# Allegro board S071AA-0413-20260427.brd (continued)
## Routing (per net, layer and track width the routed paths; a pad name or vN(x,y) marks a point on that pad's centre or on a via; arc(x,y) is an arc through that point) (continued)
GNDA_REG: length 18.7
  L11_DPS w0.076: 147.87,222.61 147.87,214.68 v2(148.32,214.23)
  L11_DPS w0.203: 147.87,222.61 147.87,222.94 146.01,224.79 v1(146.01,230.92)
  BOTTOM w0.152: SH12.1 v1(146.01,230.92)
  vias: v1(92.98,288.29) v1(92.98,283.21) v1(93.76,279.15) v1(101.34,279.15) v1(102.12,288.29) v1(102.12,283.21) v1(106.38,285.83) v1(106.38,283.04) v1(112.45,271.67) v1(112.45,268.87) v1(122.94,258.74) v1(122.94,255.95) v1(136.51,248.16) v1(136.51,245.36) v1(177.02,218.6)
CSDPS225GS1: length 13.4
  L11_DPS w0.203: 129.81,335.28 128.61,336.48 126.7,336.48 125.85,335.62 125.85,329.08 CSDPS225.D2
CSDPS225GS16: length 13.3
  L11_DPS w0.203: 91.71,327.66 93.05,326.31 94.7,326.31 95.47,327.09 95.47,334.06 CSDPS225.A15
CSDPS225PS2: length 8.7
  L11_DPS w0.203: CSDPS225.A2 128.52,334.03 128.52,328.95 129.81,327.66
CSDPS225PS16: length 8.7
  L11_DPS w0.203: CSDPS225.A16 92.97,334.02 92.97,328.94 94.25,327.66
CSDPS229GS16: length 13.4
  L11_DPS w0.203: 18.05,327.66 16.63,329.08 16.63,335.62 17.48,336.48 19.39,336.48 CSDPS229.A15
CSDPS229PS16: length 8.7
  L11_DPS w0.203: 20.59,327.66 19.3,328.95 19.3,334.03 CSDPS229.A16
CSDPS425GS1: length 13.4
  L11_DPS w0.203: 129.81,345.44 128.61,346.64 126.7,346.64 125.85,345.78 125.85,339.24 CSDPS425.D2
CSDPS425GS15: length 13.3
  L11_DPS w0.203: CSDPS425.D16 93.05,336.47 94.7,336.47 95.47,337.25 95.47,344.22 94.25,345.44
CSDPS425PS2: length 8.7
  L11_DPS w0.203: 129.81,337.82 128.52,339.11 128.52,344.19 CSDPS425.A2
CSDPS425PS16: length 8.7
  L11_DPS w0.203: CSDPS425.A16 92.97,344.18 92.97,339.1 94.25,337.82
CSDPS429GS1: length 13.4
  L11_DPS w0.203: CSDPS429.D2 52.19,339.24 52.19,345.78 53.04,346.64 54.95,346.64 56.15,345.44
CSDPS429GS15: length 13.4
  L11_DPS w0.203: 20.59,345.44 19.39,346.64 17.48,346.64 16.63,345.78 16.63,339.24 CSDPS429.D16
CSDPS429PS2: length 8.7
  L11_DPS w0.203: CSDPS429.A2 54.86,344.19 54.86,339.11 56.15,337.82
CSDPS429PS16: length 8.7
  L11_DPS w0.203: 20.59,337.82 19.3,339.11 19.3,344.19 CSDPS429.A16
D231_MCB1_CT2: length 82.1
  L03_DIG w0.132: D231.17 13.04,370.91 13.04,314.98 v2(29.05,298.96)
D431_MCB1_A+: length 354.8
  L24_DIG w0.132: 74.57,190.88 73.7,191.75 54.6,191.75 K3.5 50.83,191 ; 74.57,190.88 K2.5 78.23,191.75 97.32,191.75 97.96,191.11 ; 74.57,190.88 74.57,195.71 K10.5 74.31,198.75 74.31,203.08 K12.5 74.52,206.17 74.52,210.9 K14.5 ; 97.96,191.11 K1.5 ; 97.96,191.11 97.96,195.48 K11.5 97.91,198.78 97.91,203.05 K13.5 97.96,206.35 97.96,210.72 K15.5 ; K7.5 50.8,210.8 50.8,206.27 K8.5 50.84,203.22 50.84,198.6 K9.5 50.83,195.59 50.83,191 ; D431.16 12.83,375.78 12.83,257.85 24.32,246.35 24.32,222.51 26.29,220.54 26.29,214.77 K4.5 27.08,210.71 27.08,206.36 K5.5 27.03,203.04 27.03,198.79 K6.5 27.21,195.6 27.21,190.99 K16.5 31.37,192.14 49.69,192.14 50.83,191
D431_MCB1_A-: length 328.2
  L24_DIG w0.132: 74.46,221.46 74.21,221.71 54.09,221.71 K18.5 50.62,221.68 ; 74.46,221.46 K19.5 77.84,221.84 97.71,221.84 98.16,221.39 ; 74.46,221.46 74.46,226.09 K23.5 74.41,229.13 74.41,233.66 K27.5 74.41,236.75 74.41,241.28 K31.5 ; D431.15 19.3,382.25 19.3,376.96 16.82,374.48 14.65,374.48 13.39,373.22 13.39,258.16 K29.5 27.06,241.16 27.06,236.86 K25.5 27.08,233.57 27.08,229.22 K21.5 26.88,225.75 26.88,221.8 K17.5 30.92,222.17 30.92,222.31 31.05,222.44 49.86,222.44 50.62,221.68 ; 98.16,221.39 K20.5 ; 98.16,221.39 98.16,226.16 K24.5 98,229.16 98,233.63 K28.5 98,236.78 98,241.25 K32.5 ; 50.62,221.68 50.62,225.87 K22.5 50.77,229.15 50.77,233.64 K26.5 50.57,236.97 50.57,241.06 K30.5
D431_MCB1_C+: length 380.2
  L24_DIG w0.132: K33.5 114.84,160 118.87,160 K37.5 122.61,159.85 133.96,159.85 K34.5 137.88,159.82 141.55,159.82 K38.5 ; K33.5 110.64,164.2 110.64,254.21 107.34,257.52 66.12,257.52 61.47,262.17 61.47,375.78 57.53,379.72 29.49,379.72 D431.12 ; K33.5 110.07,158.83 110.07,141.66 K35.5 115.17,136.56 134.04,136.56 K36.5
D431_MCB1_C-: length 387.1
  L24_DIG w0.132: D431.11 31.92,382.37 57.38,382.37 63.39,376.36 63.39,263.89 68.09,259.19 107.89,259.19 111.8,255.28 111.8,168.16 113.46,166.49 123.59,166.49 K41.5 129.57,163.08 149.86,163.08 K42.5 149.26,159.91 149.26,140.32 149.9,139.67 ; 149.9,139.67 144.77,139.67 K40.5 142.21,139.75 134.6,139.75 134.41,139.94 129.54,139.94 K43.5 127.05,139.92 121.9,139.92 K39.5 ; 149.9,139.67 K44.5
D431_MCB1_CT1: length 94
  L03_DIG w0.132: v2(29.05,297.94) 12.08,314.91 12.08,380.11 D431.17
D11616: length 208.2
  L03_DIG w0.132: v2(29.9,298.96) 130.42,298.96 160.24,328.78 160.24,386.03 D116.16
  BOTTOM w0.152: TR2.2 v2(29.9,298.96)
GPDPS1_1F: length 9.8
  L16_DPS w0.203: 241.57,18.24 DPS1.C03 ; DPS1.C03 241.57,19.86 ; DPS1.C03 240.76,19.05 ; DPS1.C03 242.38,19.05 ; 240.76,16.51 DPS1.B03 ; DPS1.B03 241.57,15.7 ; DPS1.B03 242.38,16.51 ; DPS1.B03 241.57,17.32 ; 241.57,13.16 DPS1.A03 ; DPS1.A03 241.57,14.78 ; DPS1.A03 242.38,13.97 ; DPS1.A03 240.76,13.97
  vias: v1(205.76,294.62)
GPDPS1_1GS: length 464.1
  L16_DPS w0.203: v1(194.58,294.32) 195.74,293.16 208.28,293.16 210.57,290.88 210.57,221.48 200.95,211.86 196.23,211.86 195.11,212.98 187.82,212.98 186.7,211.86 166.3,211.86 164.02,209.58 160.74,209.58 155.85,204.69 155.85,184.25 227.3,112.8 227.3,77.97 236.6,68.68 269.84,68.68 273.63,64.9 273.63,11.23 272.05,9.65 250.9,9.65 248.15,12.41 248.15,20.43 247.22,21.35 239.43,21.35 237.78,19.7 237.78,15.22 DPS1.A02
GPDPS1_1S: length 458.1
  L16_DPS w0.203: DPS1.C02 240.5,20.52 247.06,20.52 247.72,19.86 247.72,11.61 250.28,9.05 272.62,9.05 276.02,12.44 276.02,65.79 272.21,69.6 237.13,69.6 228.55,78.18 228.55,113.75 156.35,185.95 156.35,202.99 162.26,208.9 164.43,208.9 166.79,211.26 186.91,211.26 188.01,212.36 194.82,212.36 195.92,211.26 201.28,211.26 211.32,221.3 211.32,291.23 208.83,293.71 197.73,293.71 v1(197.12,294.32)
GPDPS1_2F: length 9.8
  L16_DPS w0.203: 250.92,13.97 DPS1.A07 ; DPS1.A07 251.73,13.16 ; DPS1.A07 251.73,14.78 ; DPS1.A07 252.54,13.97 ; DPS1.B07 252.54,16.51 ; DPS1.B07 250.92,16.51 ; DPS1.B07 251.73,17.32 ; DPS1.B07 251.73,15.7 ; DPS1.C07 252.54,19.05 ; DPS1.C07 251.73,18.24 ; DPS1.C07 251.73,19.86 ; DPS1.C07 250.92,19.05
  vias: v1(172.23,294.62)
GPDPS1_2GS: length 689.7
  L16_DPS w0.203: DPS1.A06 249.19,12.7 250.76,11.13 259.26,11.13 260.78,12.65 260.78,31.49 258.13,34.15 258.13,36.2 257.51,36.82 13.78,36.82 11.83,38.77 11.83,179.93 11.16,180.6 11.16,266.13 33.37,288.34 33.37,295.23 38.56,300.42 161.72,300.42 164.1,298.04 v1(164.1,294.32)
GPDPS1_2S: length 695.9
  L16_DPS w0.203: v1(166.64,294.32) 166.64,296.81 162.46,300.99 38.22,300.99 32.73,295.51 32.73,290.19 10.35,267.81 10.35,38.08 14.23,34.2 257.2,34.2 260.36,31.04 260.36,13.06 259.03,11.73 251.15,11.73 250.41,12.47 250.41,17.83 DPS1.C06
GPDPS1_3F: length 9.8
  L16_DPS w0.203: 266.16,16.51 DPS1.B13 ; DPS1.B13 266.97,15.7 ; DPS1.B13 266.97,17.32 ; DPS1.B13 267.78,16.51 ; 266.97,18.24 DPS1.C13 ; DPS1.C13 267.78,19.05 ; DPS1.C13 266.16,19.05 ; DPS1.C13 266.97,19.86 ; DPS1.A13 266.97,14.78 ; DPS1.A13 267.78,13.97 ; DPS1.A13 266.97,13.16 ; DPS1.A13 266.16,13.97
  vias: v1(48.28,294.62)
GPDPS1_3GS: length 535.8
  L16_DPS w0.203: DPS1.A12 263.26,15.14 263.26,29.85 260.6,32.5 260.6,41 259.88,41.72 20.76,41.72 12.45,50.04 12.45,264.53 38.01,290.09 38.01,293.41 v1(37.1,294.32)
GPDPS1_3S: length 532.3
  L16_DPS w0.203: DPS1.C12 264.43,30.28 263.14,31.57 263.14,41.15 261.99,42.3 21.25,42.3 13.16,50.38 13.16,262.71 40.82,290.37 40.82,293.13 v1(39.64,294.32)
GPDPS1_4F: length 9.8
  L11_DPS w0.203: 277.13,15.7 DPS1.B17 ; DPS1.B17 277.13,17.32 ; DPS1.B17 277.94,16.51 ; DPS1.B17 276.32,16.51 ; 276.32,13.97 DPS1.A17 ; DPS1.A17 277.13,13.16 ; DPS1.A17 277.94,13.97 ; DPS1.A17 277.13,14.78 ; 277.13,18.24 DPS1.C17 ; DPS1.C17 277.13,19.86 ; DPS1.C17 277.94,19.05 ; DPS1.C17 276.32,19.05
  vias: v1(149.88,294.62)
GPDPS1_4GS: length 413.6
  L11_DPS w0.203: v1(138.7,294.32) 140.34,294.32 141.44,293.22 268.44,293.22 270.15,291.51 270.15,104.63 268.27,102.75 268.27,24.5 273.35,19.42 273.35,15.21 DPS1.A16
GPDPS1_4S: length 405
  L11_DPS w0.203: DPS1.C16 270.76,22.88 270.76,291.91 268.97,293.71 141.85,293.71 v1(141.24,294.32)
GPDPS1_TRVB-: length 5.2
  TOP w0.152: SB1.2 258.04,13.12 258.04,15.28 DPS1.B09
GPDPS2_1F: length 9.8
  L11_DPS w0.203: 198.39,411.94 DPS2.B03 ; DPS2.B03 197.58,412.75 ; DPS2.B03 198.39,413.56 ; DPS2.B03 199.2,412.75 ; DPS2.A03 198.39,416.1 ; DPS2.A03 197.58,415.29 ; DPS2.A03 198.39,414.48 ; DPS2.A03 199.2,415.29 ; 197.58,410.21 DPS2.C03 ; DPS2.C03 198.39,411.02 ; DPS2.C03 198.39,409.4 ; DPS2.C03 199.2,410.21
  vias: v1(127.02,294.62)
GPDPS2_1GS: length 214.3
  L11_DPS w0.203: v1(115.84,294.32) 115.84,310.2 110.58,315.46 110.58,404.82 111.16,405.4 187.98,405.4 191.79,409.21 191.79,416.47 193.21,417.89 199.3,417.89 200.93,416.25 DPS2.A02
GPDPS2_1S: length 218.6
  L11_DPS w0.203: DPS2.C02 199.83,411.31 199.83,416.51 199.05,417.29 193.49,417.29 192.27,416.07 192.27,408.76 188.36,404.85 111.63,404.85 111.01,404.23 111.01,315.88 118.38,308.51 v1(118.38,294.32)
GPDPS2_2F: length 9.8
  L11_DPS w0.203: 187.42,412.75 DPS2.B07 ; DPS2.B07 189.04,412.75 ; DPS2.B07 188.23,411.94 ; DPS2.B07 188.23,413.56 ; DPS2.A07 189.04,415.29 ; DPS2.A07 188.23,416.1 ; DPS2.A07 188.23,414.48 ; DPS2.A07 187.42,415.29 ; DPS2.C07 189.04,410.21 ; DPS2.C07 188.23,411.02 ; DPS2.C07 188.23,409.4 ; DPS2.C07 187.42,410.21
  vias: v1(99.08,294.62)
GPDPS2_2GS: length 229.2
  L11_DPS w0.203: DPS2.A06 190.77,417.4 187.98,420.2 92.67,420.2 87.9,415.42 v1(87.9,294.32)
GPDPS2_2S: length 229.1
  L11_DPS w0.203: DPS2.C06 189.63,411.35 189.63,416.76 187.87,418.52 93.87,418.52 90.44,415.08 v1(90.44,294.32)
GPDPS2_3F: length 9.8
  L16_DPS w0.203: DPS2.B13 173.8,412.75 ; DPS2.B13 172.99,413.56 ; DPS2.B13 172.99,411.94 ; DPS2.B13 172.18,412.75 ; DPS2.A13 173.8,415.29 ; DPS2.A13 172.18,415.29 ; DPS2.A13 172.99,414.48 ; DPS2.A13 172.99,416.1 ; DPS2.C13 173.8,410.21 ; DPS2.C13 172.18,410.21 ; DPS2.C13 172.99,409.4 ; DPS2.C13 172.99,411.02
  vias: v1(235.73,294.62)
GPDPS2_3GS: length 184
  L16_DPS w0.203: v1(227.6,294.32) 227.6,297.8 211.64,313.76 211.64,378.45 202.77,387.32 168.65,387.32 166.09,389.87 164.8,389.87 164.1,390.58 164.1,416.38 166.73,419.01 173.27,419.01 175.53,416.75 DPS2.A12
GPDPS2_3S: length 185.9
  L16_DPS w0.203: DPS2.C12 174.41,411.33 174.41,417.08 173.39,418.1 167.49,418.1 166.32,416.92 166.32,390.46 166.96,389.82 202.01,389.82 212.59,379.24 212.59,314.52 230.14,296.97 v1(230.14,294.32)
GPDPS2_4F: length 5.1
  L09_DPS w0.203: DPS2.C17 DPS2.B17 DPS2.A17
GPDPS2_TRVB-: length 5.2
  TOP w0.152: SB13.2 181.88,416.26 181.88,414.02 DPS2.B09
GPDPS3_1F: length 5.1
  L09_DPS w0.203: DPS3.C03 DPS3.B03 DPS3.A03
GPDPS3_2F: length 5.1
  L09_DPS w0.203: DPS3.A07 DPS3.B07 DPS3.C07
GPDPS3_3F: length 5.1
  L09_DPS w0.203: DPS3.A13 DPS3.B13 DPS3.C13
GPDPS3_4F: length 5.1
  L09_DPS w0.203: DPS3.A17 DPS3.B17 DPS3.C17
GPDPS3_TRVB-: length 5.6
  TOP w0.152: SB14.2 110.73,12.74 110.73,15.27 DPS3.B09
GPDPS8_1F: length 5.1
  L09_DPS w0.203: DPS8.A03 DPS8.B03 DPS8.C03
GPDPS8_2F: length 5.1
  L09_DPS w0.203: DPS8.C07 DPS8.B07 DPS8.A07
GPDPS8_3F: length 5.1
  L09_DPS w0.203: DPS8.A13 DPS8.B13 DPS8.C13
GPDPS8_4F: length 5.1
  L09_DPS w0.203: DPS8.A17 DPS8.B17 DPS8.C17
GPDPS8_TRVB-: length 5
  TOP w0.152: DPS8.B09 34.58,413.99 34.58,416.14 SB15.2
S1_ADC1_VIN[0]: length 36
  L20_DIG w0.076: v2(141.92,207.03) 141.57,206.68
  L20_DIG w0.132: K1.8 119.9,192.02 119.9,199.14 127.22,206.45 141.34,206.45 141.57,206.68
S1_ADC1_VIN[1]: length 58.9
  L20_DIG w0.076: v2(141.92,207.83) 141.52,207.43 138.29,207.43
  L20_DIG w0.132: K2.8 96.69,192.43 96.69,197.79 98.85,199.95 118.53,199.95 126.01,207.43 138.29,207.43
S1_ADC1_VIN[2]: length 86.9
  L20_DIG w0.076: 138.29,208.23 141.52,208.23 v2(141.92,208.63)
  L20_DIG w0.132: K3.8 73.02,192.38 73.02,204.7 74.92,206.6 122.95,206.6 124.58,208.23 138.29,208.23
S1_ADC1_VIN[3]: length 96.5
  L18_DIG w0.076: v2(141.12,208.63) 140.72,208.23 138.29,208.23
  L18_DIG w0.132: 138.29,208.23 50.61,208.23 K4.8
S1_ADC1_VIN[4]: length 95.9
  L18_DIG w0.076: 138.29,207.43 140.72,207.43 v2(141.12,207.83)
  L18_DIG w0.132: 138.29,207.43 49.2,207.43 K5.8
S1_ADC1_VIN[5]: length 98.7
  L18_DIG w0.076: 140.77,206.68 v2(141.12,207.03)
  L18_DIG w0.132: K6.8 49.06,199.67 119.07,199.67 125.91,206.51 140.6,206.51 140.77,206.68
S1_ADC1_VIN[6]: length 72.1
  L07_DIG w0.076: 138.29,208.23 139.92,208.23 v2(140.32,208.63)
  L07_DIG w0.132: K7.8 74.23,208.23 138.29,208.23
S1_ADC1_VIN[7]: length 71.5
  L07_DIG w0.076: 138.29,207.43 139.92,207.43 v2(140.32,207.83)
  L07_DIG w0.132: 138.29,207.43 72.83,207.43 K8.8
S1_ADC1_VIN[8]: length 74.3
  L07_DIG w0.076: v2(140.32,207.03) 139.97,206.68
  L07_DIG w0.132: 139.97,206.68 139.82,206.53 125.52,206.53 118.96,199.97 72.99,199.97 K9.8
S1_ADC1_VIN[9]: length 49.9
  L05_DIG w0.076: 139.17,206.68 v2(139.52,207.03)
  L05_DIG w0.132: 139.17,206.68 138.94,206.45 125.64,206.45 119.09,199.9 96.54,199.9 K10.8
S1_ADC1_VIN[10]: length 25.5
  L03_DIG w0.132: v2(138.72,207.03) 127.29,207.03 K11.8
S1_ADC1_VIN[11]: length 47.1
  L05_DIG w0.076: v2(139.52,207.83) 139.12,207.43 138.29,207.43
  L05_DIG w0.132: K12.8 96.45,207.43 138.29,207.43
S1_ADC1_VIN[12]: length 22.6
  L03_DIG w0.132: K13.8 120.47,207.83 v2(138.72,207.83)
S1_ADC1_VIN[13]: length 47.6
  L05_DIG w0.076: v2(139.52,208.63) 139.12,208.23 138.29,208.23
  L05_DIG w0.132: 138.29,208.23 97.86,208.23 K14.8
S1_ADC1_VIN[14]: length 22.9
  L03_DIG w0.132: v2(138.72,208.63) 121.08,208.63 K15.8
S1_ADC1_VIN[15]: length 111.2
  L20_DIG w0.076: 138.29,209.03 141.52,209.03 v2(141.92,209.43)
  L20_DIG w0.132: K16.8 49.6,192.58 49.6,205.36 52.19,207.95 122.32,207.95 123.4,209.03 138.29,209.03
S1_ADC1_VIN[16]: length 99.3
  L18_DIG w0.076: 138.29,209.03 140.72,209.03 v2(141.12,209.43)
  L18_DIG w0.132: K17.8 51.96,214.5 119.12,214.5 124.59,209.03 138.29,209.03
S1_ADC1_VIN[17]: length 74.9
  L07_DIG w0.076: 138.29,209.03 139.92,209.03 v2(140.32,209.43)
  L07_DIG w0.132: K18.8 75.66,214.43 119.22,214.43 124.61,209.03 138.29,209.03
S1_ADC1_VIN[18]: length 50.5
  L05_DIG w0.076: v2(139.52,209.43) 139.12,209.03 138.29,209.03
  L05_DIG w0.132: 138.29,209.03 125.58,209.03 120.01,214.6 99.1,214.6 K19.8
S1_ADC1_VIN[19]: length 25.7
  L03_DIG w0.132: K20.8 127.9,209.43 v2(138.72,209.43)
S1_ADC1_VIN[20]: length 102.1
  L18_DIG w0.076: v2(141.12,210.23) 140.72,209.83 138.29,209.83
  L18_DIG w0.132: K21.8 51.58,222.5 107.51,222.5 114.29,215.72 120.41,215.72 126.3,209.83 138.29,209.83
S1_ADC1_VIN[21]: length 77.7
  L07_DIG w0.076: 138.29,209.83 139.92,209.83 v2(140.32,210.23)
  L07_DIG w0.132: 138.29,209.83 126,209.83 120.03,215.8 110.86,215.8 104.66,222 75.71,222 K22.8
S1_ADC1_VIN[22]: length 55.2
  L05_DIG w0.076: v2(139.52,210.23) 139.12,209.83 138.29,209.83
  L05_DIG w0.132: K23.8 98.8,222.53 117.47,222.53 118.84,221.16 118.84,217.91 126.91,209.83 138.29,209.83
S1_ADC1_VIN[23]: length 32
  L03_DIG w0.132: v2(138.72,210.23) 128.9,210.23 119.04,220.09 119.04,225.91 K24.8
S1_ADC1_VIN[24]: length 110.3
  L18_DIG w0.076: v2(141.12,211.03) 140.72,210.63 138.29,210.63
  L18_DIG w0.132: K25.8 51.48,230.23 117.62,230.23 119.42,228.42 119.42,219.25 128.04,210.63 138.29,210.63
S1_ADC1_VIN[25]: length 86.2
  L07_DIG w0.076: 138.29,210.63 139.92,210.63 v2(140.32,211.03)
  L07_DIG w0.132: 138.29,210.63 127.49,210.63 119.37,218.74 119.37,228.37 117.74,230 75.33,230 K26.8
S1_ADC1_VIN[26]: length 61.6
  L05_DIG w0.076: 138.29,210.63 139.12,210.63 v2(139.52,211.03)
  L05_DIG w0.132: K27.8 98.87,230.07 118.02,230.07 119.57,228.52 119.57,219.18 128.12,210.63 138.29,210.63
S1_ADC1_VIN[27]: length 38.5
  L03_DIG w0.132: K28.8 119.85,232.71 119.85,220.5 129.32,211.03 v2(138.72,211.03)
S1_ADC1_VIN[28]: length 116.5
  L18_DIG w0.076: v2(141.12,211.83) 140.72,211.43 138.29,211.43
  L18_DIG w0.132: 138.29,211.43 129.45,211.43 120.56,220.32 120.56,235.15 117.85,237.87 51.45,237.87 K29.8
S1_ADC1_VIN[29]: length 92.5
  L07_DIG w0.076: 138.29,211.43 139.92,211.43 v2(140.32,211.83)
  L07_DIG w0.132: 138.29,211.43 129.07,211.43 120.59,219.91 120.59,235.51 118.3,237.79 75.15,237.79 K30.8
S1_ADC1_VIN[30]: length 68.1
  L05_DIG w0.076: v2(139.52,211.83) 139.12,211.43 138.29,211.43
  L05_DIG w0.132: K31.8 99.02,237.54 119.27,237.54 120.54,236.27 120.54,220.6 129.71,211.43 138.29,211.43
S1_ADC1_VIN[31]: length 45.2
  L03_DIG w0.132: K32.8 120.64,239.55 120.64,220.7 129.51,211.83 v2(138.72,211.83)
S1_ADC2_VIN[0]: length 43.1
  L03_DIG w0.132: v2(143.52,207.03) 143.52,204.9 122.14,183.52 116.99,183.52 K33.8
S1_ADC2_VIN[1]: length 31.7
  L05_DIG w0.076: v2(143.52,207.83) 143.92,207.43 143.92,206.68
  L05_DIG w0.132: 143.92,206.68 143.92,187.59 K34.8
S1_ADC2_VIN[2]: length 65.1
  L07_DIG w0.076: v2(143.52,208.63) 143.92,208.23 143.92,206.68
  L07_DIG w0.132: K35.8 118.23,161.65 118.23,179.53 143.92,205.22 143.92,206.68
S1_ADC2_VIN[3]: length 56.7
  L18_DIG w0.076: 143.92,206.68 143.92,209.03 v2(143.52,209.43)
  L18_DIG w0.132: 143.92,206.68 143.92,185.89 140.87,182.84 140.87,161.18 K36.8
S1_ADC2_VIN[4]: length 37.2
  L03_DIG w0.132: v2(144.32,207.03) 144.32,203.23 K37.8
S1_ADC2_VIN[5]: length 28.9
  L05_DIG w0.076: 144.72,206.68 144.72,207.43 v2(144.32,207.83)
  L05_DIG w0.132: 144.72,206.68 144.72,180.77 K38.8
S1_ADC2_VIN[6]: length 62.3
  L07_DIG w0.076: 144.72,206.68 144.72,208.23 v2(144.32,208.63)
  L07_DIG w0.132: K39.8 125.7,161.5 125.7,182.48 144.72,201.5 144.72,206.68
S1_ADC2_VIN[7]: length 56.7
  L18_DIG w0.076: v2(144.32,209.43) 144.72,209.03 144.72,206.68
  L18_DIG w0.132: 144.72,206.68 144.72,186.54 148.08,183.18 148.08,160.76 K40.8
S1_ADC2_VIN[8]: length 34.4
  L03_DIG w0.132: K41.8 145.12,196.41 v2(145.12,207.03)
S1_ADC2_VIN[9]: length 30.7
  L05_DIG w0.076: v2(145.12,207.83) 145.52,207.43 145.52,206.68
  L05_DIG w0.132: 145.52,206.68 145.52,185.2 K42.8
S1_ADC2_VIN[10]: length 59.5
  L07_DIG w0.076: 145.52,206.68 145.52,208.23 v2(145.12,208.63)
  L07_DIG w0.132: K43.8 133.35,161.52 133.35,180.8 145.52,192.97 145.52,206.68
S1_ADC2_VIN[11]: length 55.7
  L18_DIG w0.076: 145.52,206.68 145.52,209.03 v2(145.12,209.43)
  L18_DIG w0.132: K44.8 149.13,158.23 149.13,183.36 145.52,186.97 145.52,206.68
S1_CBIT001: length 380.3
  TOP w0.305: K1.1 114.82,184.4 LD1.2
  L13_CBIT w0.305: K1.1 114.12,186.94 104.01,197.06 104.01,255.04 110.44,261.47 242.42,261.47 256.98,276.04 256.98,288.57 258.18,289.76 258.18,410.31 259.35,411.48
S1_CBIT002: length 207
  TOP w0.305: K2.1 91.2,184.4 LD2.2
  L13_CBIT w0.305: K2.1 93.74,155.57 159.5,89.81 159.5,18.57 162.83,15.24
S1_CBIT003: length 225.6
  TOP w0.305: K3.1 67.58,184.4 LD3.2
  L13_CBIT w0.305: K3.1 70.12,176.91 158.09,88.94 158.09,16.42 161.3,13.2 165.87,13.2 167.91,15.24
S1_CBIT004: length 254.6
  TOP w0.305: LD4.2 43.96,207.26 K4.1
  L13_CBIT w0.305: 99.33,414.02 98.07,412.76 98.07,326.98 93.13,322.03 66.84,322.03 40.65,295.84 40.65,212.99 43.84,209.8 K4.1
S1_CBIT005: length 261.5
  TOP w0.305: LD5.2 43.96,199.64 K5.1
  L13_CBIT w0.305: 96.79,411.48 95.56,410.25 95.56,327.47 92.3,324.21 63.57,324.21 38.88,299.52 38.88,207.16 43.85,202.18 K5.1
S1_CBIT006: length 285.8
  TOP w0.305: LD6.2 43.96,192.02 K6.1
  L13_CBIT w0.305: K6.1 44.05,194.56 36.28,202.34 36.28,301.35 86.74,351.81 86.74,414.26 89.67,417.19 113.94,417.19 117.11,414.02
S1_CBIT007: length 246
  TOP w0.305: K7.1 67.58,207.26 LD7.2
  L13_CBIT w0.305: K7.1 67.46,209.8 63.59,213.67 63.59,291.52 75.53,303.45 94.74,303.45 115.92,324.63 115.92,410.29 117.11,411.48
S1_CBIT008: length 259.7
  TOP w0.305: K8.1 67.58,199.64 LD8.2
  L13_CBIT w0.305: 114.57,414.02 113.15,412.6 113.15,324.62 94.5,305.97 74.11,305.97 58.91,290.77 58.91,210.75 67.47,202.18 K8.1
S1_CBIT009: length 265.2
  TOP w0.305: K9.1 67.58,192.02 LD9.2
  L13_CBIT w0.305: K9.1 67.67,194.56 57.39,204.85 57.39,292.86 73.22,308.69 94.25,308.69 110.77,325.22 110.77,410.23 112.03,411.48
S1_CBIT010: length 252.8
  TOP w0.305: LD10.2 91.2,192.02 K10.1
  L13_CBIT w0.305: K10.1 91.3,194.56 81.28,204.58 81.28,272.6 128.61,319.93 128.61,412.82 129.81,414.02
S1_CBIT011: length 373.6
  TOP w0.305: LD11.2 114.82,192.02 K11.1
  L13_CBIT w0.305: 261.89,414.02 260.66,412.8 260.66,275.48 243.22,258.04 112.22,258.04 106.01,251.83 106.01,203.47 114.92,194.56 K11.1
S1_CBIT012: length 362.5
  TOP w0.305: LD12.2 91.2,199.64 K12.1
  L13_CBIT w0.305: 244.11,411.48 242.83,410.2 242.83,305.2 234.03,296.41 234.03,287.91 222.52,276.4 95.08,276.4 83.95,265.26 83.95,209.33 91.09,202.18 K12.1
S1_CBIT013: length 362.9
  TOP w0.305: LD13.2 114.82,199.64 K13.1
  L13_CBIT w0.305: K13.1 114.72,202.18 107.81,209.09 107.81,247.88 114.02,254.08 244.78,254.08 262.04,271.35 262.04,291.22 263.18,292.36 263.18,410.23 264.43,411.48
S1_CBIT014: length 355.5
  TOP w0.305: LD14.2 91.2,207.26 K14.1
  L13_CBIT w0.305: K14.1 91.08,209.8 87.62,213.26 87.62,264.38 97.39,274.14 224.92,274.14 237.09,286.31 237.09,296.36 245.38,304.65 245.38,412.75 246.65,414.02
S1_CBIT015: length 357.1
  TOP w0.305: K15.1 114.82,207.26 LD15.2
  L13_CBIT w0.305: 266.97,411.48 265.8,410.31 265.8,292.53 266.85,291.47 266.85,269.97 249.06,252.18 115.75,252.18 109.78,246.21 109.78,214.73 114.7,209.8 K15.1
S1_CBIT016: length 307.6
  TOP w0.305: LD16.2 43.96,184.4 K16.1
  L13_CBIT w0.305: K16.1 43.5,186.94 33.74,196.7 33.74,303.14 84.3,353.7 84.3,415.59 88.18,419.47 119.28,419.47 124.73,414.02
S1_CBIT017: length 243.5
  TOP w0.305: LD17.2 43.96,214.88 K17.1
  L13_CBIT w0.305: 101.87,411.48 100.61,410.22 100.61,326.79 93.47,319.65 67.83,319.65 43.59,295.41 43.59,281.75 42.24,280.4 42.24,219.55 44.36,217.42 K17.1
S1_CBIT018: length 236.1
  TOP w0.305: K18.1 67.58,214.88 LD18.2
  L13_CBIT w0.305: K18.1 67.98,217.42 66.13,219.27 66.13,289.12 78.04,301.02 95.62,301.02 118.15,323.55 118.15,409.98 119.65,411.48
S1_CBIT019: length 349.7
  TOP w0.305: LD19.2 91.2,214.88 K19.1
  L13_CBIT w0.305: 249.19,411.48 247.94,410.23 247.94,304.67 245.56,302.29 245.56,281.32 238.2,273.96 234.81,273.96 233.19,272.34 100.39,272.34 89.48,261.43 89.48,219.55 91.61,217.42 K19.1
S1_CBIT020: length 352.3
  TOP w0.305: K20.1 114.82,214.88 LD20.2
  L13_CBIT w0.305: 269.51,414.02 268.3,412.81 268.3,282.41 269.31,281.4 269.31,268.32 249.63,248.64 141.06,248.64 140.59,249.11 135.93,249.11 135.46,248.64 115.37,248.64 111.43,244.7 111.43,221.23 115.23,217.42 K20.1
S1_CBIT021: length 234.8
  TOP w0.305: LD21.2 43.96,222.5 K21.1
  L13_CBIT w0.305: K21.1 50.7,229.25 50.7,276.98 52.53,278.81 52.53,292.25 71.77,311.49 94.13,311.49 108.19,325.55 108.19,412.72 109.49,414.02
S1_CBIT022: length 216.8
  TOP w0.305: K22.1 67.58,222.5 LD22.2
  L13_CBIT w0.305: K22.1 74.32,229.25 74.32,268.3 125.8,319.78 125.8,410.01 127.27,411.48
S1_CBIT023: length 341
  TOP w0.305: LD23.2 91.2,222.5 K23.1
  L13_CBIT w0.305: K23.1 97.94,229.25 97.94,253.81 107.74,263.61 139.87,263.61 140.88,262.59 145.06,262.59 146.08,263.61 239.07,263.61 255.53,280.07 255.53,412.74 256.81,414.02
S1_CBIT024: length 342
  TOP w0.305: K24.1 114.82,222.5 LD24.2
  L13_CBIT w0.305: 272.05,411.48 270.91,410.34 270.91,264.83 252.82,246.75 116.31,246.75 113.14,243.58 113.14,226.88 114.97,225.04 K24.1
S1_CBIT025: length 224.5
  TOP w0.305: LD25.2 43.96,230.12 K25.1
  L13_CBIT w0.305: 106.95,411.48 105.53,410.06 105.53,325.7 93.97,314.13 70.16,314.13 49.18,293.14 49.18,235.34 K25.1
S1_CBIT026: length 208.1
  TOP w0.305: LD26.2 67.58,230.12 K26.1
  L13_CBIT w0.305: 124.73,411.48 123.35,410.1 123.35,321.01 72.8,270.46 72.8,235.34 K26.1
S1_CBIT027: length 331
  TOP w0.305: K27.1 91.2,230.12 LD27.2
  L13_CBIT w0.305: 254.27,411.48 252.97,410.18 252.97,294.22 251.77,293.03 251.77,280.4 237.98,266.62 147.36,266.62 145.97,268 140.83,268 139.45,266.62 105.1,266.62 96.59,258.11 96.59,235.52 K27.1
S1_CBIT028: length 335.9
  TOP w0.305: K28.1 114.82,230.12 LD28.2
  L13_CBIT w0.305: K28.1 120.36,235.66 120.36,239.14 123.42,242.2 258.3,242.2 279.1,263.01 279.1,290.85 275.9,294.06 275.9,412.79 277.13,414.02
S1_CBIT029: length 219.8
  TOP w0.305: LD29.2 43.96,237.74 K29.1
  L13_CBIT w0.305: K29.1 48.04,241.82 48.04,276.66 46.64,278.05 46.64,294.29 69.4,317.04 93.74,317.04 103,326.3 103,412.61 104.41,414.02
S1_CBIT030: length 212.2
  TOP w0.305: LD30.2 67.58,237.74 K30.1
  L13_CBIT w0.305: K30.1 71.66,241.82 71.66,290.52 80.13,298.99 97.53,298.99 120.81,322.27 120.81,412.64 122.19,414.02
S1_CBIT031: length 326.1
  TOP w0.305: K31.1 91.2,237.74 LD31.2
  L13_CBIT w0.305: 251.73,414.02 250.44,412.73 250.44,285.88 246.91,282.36 246.91,279.8 236.39,269.28 117.23,269.28 115.64,267.69 110.84,267.69 109.24,269.28 102.96,269.28 94.57,260.89 94.57,251.73 95.52,250.77 95.52,242.06 K31.1
S1_CBIT032: length 322.9
  TOP w0.305: LD32.2 114.82,237.74 K32.1
  L13_CBIT w0.305: K32.1 121.38,244.3 255.84,244.3 274.67,263.13 274.67,290.92 273.31,292.28 273.31,410.2 274.59,411.48
S1_CBIT033: length 201.9
  TOP w0.305: LD33.2 118.13,177.04 K33.1
  L13_CBIT w0.305: 167.91,17.78 166.71,18.98 166.71,110.39 156.87,120.23 136.69,120.23 118.97,137.96 118.97,176.19 K33.1
S1_CBIT034: length 196.7
  TOP w0.305: K34.1 140.99,177.04 LD34.2
  L13_CBIT w0.305: K34.1 141.98,176.04 141.98,137.51 146.02,133.47 162.57,133.47 181.9,114.13 181.9,19.07 180.61,17.78
S1_CBIT035: length 177
  TOP w0.305: LD35.2 118.13,153.92 K35.1
  L13_CBIT w0.305: 165.37,17.78 164.19,18.96 164.19,109.3 155.16,118.33 136.38,118.33 117.39,137.32 117.39,154.66 K35.1
S1_CBIT036: length 174.6
  TOP w0.305: LD36.2 140.99,153.67 K36.1
  L13_CBIT w0.305: K36.1 140.14,154.51 140.14,137 145.67,131.47 161.97,131.47 179.33,114.11 179.33,16.5 178.07,15.24
S1_CBIT037: length 200.7
  TOP w0.305: K37.1 125.75,177.04 LD37.2
  L13_CBIT w0.305: 172.99,17.78 171.72,19.05 171.72,112.49 159.95,124.26 140.02,124.26 126.67,137.61 126.67,176.11 K37.1
S1_CBIT038: length 189.6
  TOP w0.305: K38.1 148.61,177.04 LD38.2
  L13_CBIT w0.305: K38.1 146.07,178.36 181.25,143.17 181.25,133.56 189.59,125.23 189.59,16.6 188.23,15.24
S1_CBIT039: length 178.5
  TOP w0.305: K39.1 125.75,153.92 LD39.2
  L13_CBIT w0.305: 170.45,15.24 169.19,16.5 169.19,111.35 158.18,122.36 139.39,122.36 124.93,136.81 124.93,154.74 K39.1
S1_CBIT040: length 164.1
  TOP w0.305: LD40.2 148.61,153.67 K40.1
  L13_CBIT w0.305: K40.1 184.44,117.84 184.44,16.53 183.15,15.24
S1_CBIT041: length 201.3
  TOP w0.305: LD41.2 133.37,177.04 K41.1
  L13_CBIT w0.305: K41.1 134.31,176.09 134.31,137.45 142.99,128.77 161.34,128.77 176.82,113.29 176.82,16.53 175.53,15.24
S1_CBIT042: length 184.9
  TOP w0.305: LD42.2 156.23,177.04 K42.1
  L13_CBIT w0.305: 190.77,17.78 192.06,19.07 192.06,126.94 186.77,132.23 186.77,143.51 153.69,176.59 K42.1
S1_CBIT043: length 174.1
  TOP w0.305: LD43.2 133.37,153.92 K43.1
  L13_CBIT w0.305: K43.1 132.6,154.69 132.6,137.19 142.76,127.04 160.22,127.04 174.14,113.12 174.14,19.17 175.53,17.78
S1_CBIT044: length 160.4
  TOP w0.305: LD44.2 156.23,153.67 K44.1
  L13_CBIT w0.305: K44.1 155.5,156.21 186.91,124.8 186.91,19 185.69,17.78
S1_CBIT045: length 204.5
  TOP w0.305: K45.8 182.51,209.12 183.18,209.79 LD45.2
  L13_CBIT w0.305: 193.31,15.24 194.62,16.55 194.62,128.67 190.5,132.79 190.5,202.8 184.18,209.12 K45.8
S1_CBIT046: length 209
  TOP w0.305: K46.8 182.51,216.23 182.84,216.56 LD46.2
  L13_CBIT w0.305: K46.8 182.54,216.23 194.31,204.46 194.31,137.22 197.13,134.4 197.13,19.06 195.85,17.78
S1_CSDPS1-1F:
  vias: v1(238.78,294.62)
S1_CSDPS1-1GS: length 565.1
  L16_DPS w0.203: 18.05,337.82 16.86,336.63 7.39,336.63 1.37,342.65 1.37,424.35 3.98,426.95 59.5,426.95 65.6,420.85 79.4,420.85 86.54,427.99 205.73,427.99 212.96,420.76 274.14,420.76 282.65,412.26 282.65,305.93 270.23,293.52 226.63,293.52 225.83,294.32 v1(225.06,294.32)
S1_CSDPS1-1S: length 554
  L16_DPS w0.203: 20.59,337.82 19.37,339.04 6.51,339.04 2.13,343.42 2.13,423.54 4.58,426 59.35,426 65.27,420.08 80.49,420.08 87.8,427.4 205.35,427.4 212.87,419.88 274,419.88 282.05,411.83 282.05,306.18 269.81,293.94 233.06,293.94 v1(232.68,294.32)
S1_CSDPS2-1F:
  vias: v1(123.97,294.62)
S1_CSDPS2-1GS: length 55.5
  L09_DPS w0.203: v1(113.3,294.32) 118.34,299.36 118.34,335.57 119.04,336.26 128.83,336.26 129.81,335.28
S1_CSDPS2-1S: length 46.2
  L09_DPS w0.203: v1(120.92,294.32) 120.92,333.33 121.79,334.21 126.2,334.21 127.27,335.28
S1_CSDPS3-1F:
  vias: v1(146.83,294.62)
S1_CSDPS3-1GS: length 50.1
  L09_DPS w0.203: 127.27,337.82 128.3,336.78 133.36,336.78 136.16,333.98 v1(136.16,294.32)
S1_CSDPS3-1S: length 52
  L09_DPS w0.203: v1(143.78,294.32) 137.29,300.81 137.29,334.9 134.37,337.82 129.81,337.82
S1_CSDPS4-1F:
  vias: v1(45.23,294.62)
S1_CSDPS4-1GS: length 67.7
  L09_DPS w0.203: v1(34.56,294.32) 34.56,298.78 31.65,301.68 16.61,301.68 12.03,306.27 12.03,333.56 15.04,336.57 19.3,336.57 20.59,335.28
S1_CSDPS4-1S: length 68
  L09_DPS w0.203: v1(42.18,294.32) 42.18,297.42 37.09,302.51 17.39,302.51 13.03,306.87 13.03,332.64 14.68,334.3 17.07,334.3 18.05,335.28
S1_CSDPS5-1F:
  vias: v1(96.03,294.62)
S1_CSDPS5-1GS: length 50
  L09_DPS w0.203: 94.25,335.28 93.17,336.36 87.8,336.36 85.36,333.92 v1(85.36,294.32)
S1_CSDPS5-1S: length 45.8
  L09_DPS w0.203: v1(92.98,294.32) 87.78,299.52 87.78,333.21 88.86,334.29 90.72,334.29 91.71,335.28
S1_CSDPS6-1F:
  vias: v1(175.28,294.62)
S1_CSDPS6-1GS: length 126.4
  L16_DPS w0.203: 91.71,337.82 92.73,338.84 149.09,338.84 174.03,313.9 174.03,293.69 173.54,293.2 169.33,293.2 168.92,293.62 163.45,293.62 162.75,294.32 v1(161.56,294.32)
S1_CSDPS6-1S: length 113.1
  L16_DPS w0.203: v1(169.18,294.32) 169.84,293.66 173.03,293.66 173.42,294.05 173.42,313.09 149.93,336.58 95.49,336.58 94.25,337.82
S1_CSDPS7-1F:
  vias: v1(202.71,294.62)
S1_CSDPS7-1GS: length 236.1
  L16_DPS w0.203: v1(192.04,294.32) 192.04,299.29 185.31,306.03 185.31,325.06 184.23,326.13 184.23,353.7 183.41,354.52 182.84,354.52 180.47,356.89 162.76,356.89 144.97,374.67 88.25,374.67 86.44,376.48 68.3,376.48 61.56,369.74 61.56,341.7 56.5,336.64 54.79,336.64 53.61,337.82
S1_CSDPS7-1S: length 238
  L16_DPS w0.203: v1(199.66,294.32) 198.46,294.32 186.16,306.62 186.16,325.23 184.68,326.71 184.68,355.43 182.68,357.44 163.43,357.44 143.7,377.17 67.96,377.17 60.37,369.57 60.37,342.04 56.15,337.82
S1_DCH001: length 106.9
  L03_DIG w0.132: K1.4 68.93,156.29 68.93,132.79 55.18,119.05 55.18,100.63 53.61,99.06
S1_DCH002: length 101.4
  L05_DIG w0.132: K2.4 69.74,180.72 69.74,133.78 44.74,108.79 44.74,100.36 43.45,99.06
S1_DCH003: length 122.4
  L07_DIG w0.132: K3.4 65.75,173.53 65.75,124.18 52.34,110.77 52.34,77.47 51.07,76.2
S1_DCH004: length 142.6
  L20_DIG w0.132: 35.83,76.2 36.82,77.19 36.82,113.97 22.44,128.35 22.44,203.53 K4.4
S1_DCH005: length 131.1
  L20_DIG w0.132: K5.4 25.49,198.96 25.49,128.45 39.54,114.4 39.54,79.91 38.37,78.74
S1_DCH006: length 125.6
  L20_DIG w0.132: K6.4 47.87,175.41 47.87,120.35 44.69,117.17 44.69,79.98 43.45,78.74
S1_DCH007: length 145.6
  L07_DIG w0.132: 45.99,76.2 47.28,77.5 47.28,109.17 45.76,110.69 45.76,180.54 40.76,185.55 40.76,204.9 43.09,207.24 49.77,207.24 K7.4
S1_DCH008: length 126.6
  L07_DIG w0.132: 48.53,78.74 49.77,79.98 49.77,109.7 47.84,111.63 47.84,180.59 49.67,182.42 49.67,199.52 K8.4
S1_DCH009: length 129
  L07_DIG w0.132: K9.4 68.87,178.03 68.87,123.9 54.83,109.85 54.83,79.96 53.61,78.74
S1_DCH010: length 116.3
  L05_DIG w0.132: K10.4 73.73,192.33 67.3,192.33 64.96,189.99 64.96,133.78 42.2,111.02 42.2,97.82 40.91,96.52
S1_DCH011: length 123.6
  L03_DIG w0.132: 51.07,96.52 52.16,97.61 52.16,120.35 66.13,134.32 66.13,170.36 87.9,192.13 97.15,192.13 K11.4
S1_DCH012: length 123.3
  L05_DIG w0.132: 38.37,99.06 39.61,100.3 39.61,112.95 48.86,122.2 48.86,169.6 62.7,183.44 62.7,196.77 65.9,199.97 73.75,199.97 K12.4
S1_DCH013: length 143.2
  L03_DIG w0.132: 48.53,99.06 49.9,100.43 49.9,119.89 48.61,121.18 48.61,167.89 63.24,182.52 63.24,196.34 66.82,199.92 97.32,199.92 K13.4
S1_DCH014: length 134.8
  L05_DIG w0.132: K14.4 73.42,207.26 65.06,207.26 60.06,202.26 60.06,184.89 46.12,170.94 46.12,123.49 37.12,114.5 37.12,97.82 35.83,96.52
S1_DCH015: length 155.5
  L03_DIG w0.132: K15.4 97.3,207.52 64.81,207.52 59.53,202.23 59.53,184.99 45.94,171.4 45.94,120.45 47.11,119.28 47.11,97.64 45.99,96.52
S1_DCH016: length 116.8
  L20_DIG w0.132: 40.91,76.2 42.1,77.39 42.1,115.93 28.72,129.31 K16.4
S1_DCH017: length 148.9
  L18_DIG w0.132: 30.75,76.2 32.04,77.5 32.04,114.38 28.03,118.39 28.03,163.5 34.99,170.46 34.99,211.15 K17.4
S1_DCH018: length 155.4
  L07_DIG w0.132: 23.13,78.74 24.35,79.96 24.35,109.04 30.57,115.27 30.57,179.3 37.71,186.44 37.71,210.72 42.18,215.19 50.1,215.19 K18.4
S1_DCH019: length 156.8
  L05_DIG w0.132: 33.29,99.06 34.58,100.36 34.58,119.53 30.32,123.8 30.32,160.05 39.89,169.62 39.89,210.74 44.09,214.93 73.47,214.93 K19.4
S1_DCH020: length 182.9
  L03_DIG w0.132: 23.13,99.06 21.86,100.33 21.86,146.86 39.89,164.9 39.89,211.96 42.84,214.91 97.07,214.91 K20.4
S1_DCH021: length 155.9
  L18_DIG w0.132: 33.29,78.74 34.51,79.96 34.51,115.77 30.37,119.91 30.37,160.43 38.47,168.53 38.47,215.29 K21.4
S1_DCH022: length 168
  L07_DIG w0.132: 20.59,76.2 21.83,77.44 21.83,110.62 28.46,117.25 28.46,180.67 34.03,186.23 34.03,216.97 39.64,222.58 49.88,222.58 K22.4
S1_DCH023: length 169.3
  L05_DIG w0.132: K23.4 73.37,222.45 41.19,222.45 35.42,216.69 35.42,170.21 28.13,162.92 28.13,122.78 32.02,118.9 32.02,97.79 30.75,96.52
S1_DCH024: length 196.2
  L03_DIG w0.132: K24.4 97.09,222.55 39.16,222.55 35.45,218.85 35.45,165.23 19.34,149.12 19.34,97.76 20.59,96.52
S1_DCH025: length 157.3
  L18_DIG w0.132: K25.4 25.64,229.59 25.64,117.25 29.43,113.46 29.43,79.96 28.21,78.74
S1_DCH026: length 180.9
  L07_DIG w0.132: K26.4 49.75,230.07 27.96,230.07 25.75,227.86 25.75,119.05 19.32,112.62 19.32,80.01 18.05,78.74
S1_DCH027: length 182.9
  L05_DIG w0.132: 28.21,99.06 29.58,100.43 29.58,117.96 25.49,122.05 25.49,226.77 28.92,230.2 73.5,230.2 K27.4
S1_DCH028: length 210
  L03_DIG w0.132: 18.05,99.06 15.43,101.68 15.43,151.13 25.77,161.47 25.77,227.89 27.93,230.05 96.97,230.05 K28.4
S1_DCH029: length 168.4
  L18_DIG w0.132: K29.4 23.28,234.85 23.28,116.71 26.96,113.03 26.96,77.5 25.67,76.2
S1_DCH030: length 192
  L07_DIG w0.132: K30.4 49.72,237.67 28.06,237.67 23.21,232.82 23.21,120.65 16.8,114.25 16.8,77.5 15.51,76.2
S1_DCH031: length 195.8
  L05_DIG w0.132: K31.4 73.5,237.82 25.62,237.82 23.18,235.38 23.18,121.13 26.94,117.37 26.94,97.79 25.67,96.52
S1_DCH032: length 220.8
  L03_DIG w0.132: K32.4 97.25,237.95 28.41,237.95 23.26,232.79 23.26,163.14 13.17,153.06 13.17,98.86 15.51,96.52
S1_DCH033: length 108
  L03_DIG w0.132: 178.07,96.52 176.84,97.75 176.84,120.97 153.92,143.9 125.23,143.9 118.04,151.09 118.04,159.34 K33.4
S1_DCH034: length 93.3
  L03_DIG w0.132: 185.69,99.06 184.46,100.29 184.46,128.44 161.19,151.72 142.42,151.72 140.71,153.43 140.71,159.54 K34.4
S1_DCH035: length 71.7
  L03_DIG w0.132: K35.4 130.37,123.9 147.43,123.9 161.77,109.57 161.77,97.58 162.83,96.52
S1_DCH036: length 54.7
  L03_DIG w0.132: K36.4 144.59,132.29 148.08,132.29 169.29,111.07 169.29,100.22 170.45,99.06
S1_DCH037: length 100.8
  L03_DIG w0.132: K37.4 125.5,159.5 125.5,152.6 131.26,146.84 155.73,146.84 179.39,123.18 179.39,100.28 180.61,99.06
S1_DCH038: length 88.1
  L03_DIG w0.132: K38.4 149.88,157.98 159.03,157.98 187.01,130 187.01,97.74 188.23,96.52
S1_DCH039: length 64.3
  L03_DIG w0.132: K39.4 135.55,126.34 147.87,126.34 164.16,110.05 164.16,100.27 165.37,99.06
S1_DCH040: length 53.1
  L03_DIG w0.132: K40.4 171.77,112.72 171.77,97.73 172.99,96.52
S1_DCH041: length 98.9
  L03_DIG w0.132: 183.15,96.52 181.94,97.73 181.94,125.36 157.99,149.31 137.55,149.31 132.96,153.89 132.96,159.66 K41.4
S1_DCH042: length 81.7
  L03_DIG w0.132: K42.4 159.87,161.8 189.53,132.14 189.53,100.3 190.77,99.06
S1_DCH043: length 62.2
  L03_DIG w0.132: K43.4 140.09,129.42 148.01,129.42 166.71,110.72 166.71,97.72 167.91,96.52
S1_DCH044: length 48.4
  L03_DIG w0.132: 175.53,99.06 174.41,100.18 174.41,117.71 K44.4
S1_DCH045: length 185.7
  L03_DIG w0.076: v2(153.92,212.63) 155.01,213.72
  L03_DIG w0.132: 239.03,99.06 240.31,100.34 240.31,176.79 196.98,220.12 174.73,220.12 168.61,214 155.29,214 155.01,213.72
S1_DCH046: length 168.3
  L03_DIG w0.132: v2(153.92,211.83) 155.73,210.02 167.7,210.02 207.17,170.55 207.17,90.53 199.72,83.08 199.72,77.53 198.39,76.2
S1_DCH047: length 168.6
  L07_DIG w0.076: 154.27,214.63 152.72,214.63 v2(152.32,214.23)
  L07_DIG w0.132: 154.27,214.63 167.38,214.63 174.23,221.48 177.39,221.48 234.55,278.64 234.55,280.06 253.06,298.56 253.06,328.99 254.27,330.2
S1_DCH048: length 206.2
  L24_DIG w0.132: v2(153.92,211.03) 155.96,208.99 166.23,208.99 220.47,154.75 220.47,117.1 227.09,110.49 227.09,77.99 235.77,69.31 243.54,69.31 250.45,62.4 250.45,57.16 251.73,55.88
S1_DCH049: length 167.4
  L07_DIG w0.076: 154.27,215.43 152.72,215.43 v2(152.32,215.03)
  L07_DIG w0.132: 251.73,332.74 250.48,331.49 250.48,298.61 238.56,286.7 237.74,286.7 166.48,215.43 154.27,215.43
S1_DCH050: length 220.2
  L22_DIG w0.076: v2(153.12,212.63) 153.52,213.03 154.44,213.03 155.13,213.72
  L22_DIG w0.132: 155.13,213.72 155.19,213.77 168.76,213.77 175.28,220.28 199.29,220.28 200.67,218.91 202.06,218.91 260.66,160.3 260.66,77.43 261.89,76.2
S1_DCH051: length 173.8
  L18_DIG w0.076: 154.27,215.43 151.92,215.43 v2(151.52,215.03)
  L18_DIG w0.132: 264.43,330.2 263.12,328.89 263.12,307.55 240.41,284.84 240.41,283.74 237.81,281.14 237.05,281.14 179.19,223.28 175.67,223.28 167.82,215.43 154.27,215.43
S1_DCH052: length 207.1
  L22_DIG w0.076: 154.27,211.43 153.52,211.43 v2(153.12,211.83)
  L22_DIG w0.132: 254.27,58.42 243.84,68.85 236.41,68.85 230,75.27 230,147.64 167.1,210.54 155.16,210.54 154.27,211.43
S1_DCH053: length 242.9
  L18_DIG w0.076: 154.27,213.83 151.92,213.83 v2(151.52,213.43)
  L18_DIG w0.132: 269.51,391.16 268.33,389.98 268.33,302.43 186.83,220.93 175.59,220.93 168.49,213.83 154.27,213.83
S1_DCH054: length 205.9
  L05_DIG w0.076: v2(153.12,210.23) 153.52,209.83 154.27,209.83
  L05_DIG w0.132: 154.27,209.83 163.24,209.83 224.3,148.77 224.3,85.02 208.54,69.27 195.16,69.27 188.23,76.2
S1_DCH055: length 195.1
  L18_DIG w0.076: v2(151.52,211.03) 151.92,210.63 154.27,210.63
  L18_DIG w0.132: 266.97,96.52 262.52,92.07 234.78,92.07 222.36,104.48 222.36,153.17 164.9,210.63 154.27,210.63
S1_DCH056: length 197.9
  L22_DIG w0.076: v2(153.12,209.43) 153.52,209.03 154.27,209.03
  L22_DIG w0.132: 154.27,209.03 161.51,209.03 182.94,187.6 185.47,187.6 224.73,148.34 224.73,72.67 233.26,64.14 238.39,64.14 244.11,58.42
S1_DCH057: length 179.8
  L07_DIG w0.076: v2(152.32,211.03) 152.72,210.63 154.27,210.63
  L07_DIG w0.132: 154.27,210.63 165.26,210.63 226.38,149.51 226.38,101.55 249.19,78.74
S1_DCH058: length 200.2
  L24_DIG w0.132: 246.65,55.88 245.39,57.14 245.39,62.02 241.91,65.5 234.72,65.5 224.84,75.39 224.84,107.53 210.57,121.8 210.57,157.1 176.17,191.49 176.17,194.01 162.22,207.97 155.38,207.97 v2(153.92,209.43)
S1_DCH059: length 213.9
  L20_DIG w0.076: v2(152.32,210.23) 152.72,209.83 154.27,209.83
  L20_DIG w0.132: 154.27,209.83 163.2,209.83 220.51,152.51 220.51,64.86 207.66,52.01 197.18,52.01 193.31,55.88
S1_DCH060: length 133.6
  L03_DIG w0.132: v2(153.92,208.63) 156.3,206.25 162.42,206.25 178.95,189.72 178.95,175.5 202.16,152.28 202.16,100.29 200.93,99.06
S1_DCH061: length 174.3
  L07_DIG w0.076: v2(152.32,213.43) 152.72,213.83 154.27,213.83
  L07_DIG w0.132: 256.81,332.74 255.54,331.47 255.54,298.99 237.12,280.57 237.12,278.3 179,220.18 174.06,220.18 167.71,213.83 154.27,213.83
S1_DCH062: length 180.6
  L18_DIG w0.076: v2(151.52,214.23) 151.92,214.63 154.27,214.63
  L18_DIG w0.132: 266.97,332.74 265.82,331.59 265.82,305.36 238.23,277.77 238.23,276.63 235.82,274.21 234.96,274.21 182.73,221.99 175.51,221.99 168.16,214.63 154.27,214.63
S1_DCH063: length 202.8
  L22_DIG w0.076: v2(153.12,211.03) 153.52,210.63 154.27,210.63
  L22_DIG w0.132: 154.27,210.63 155.07,209.83 165.64,209.83 227.24,148.24 227.24,74.02 235.11,66.15 241.46,66.15 249.19,58.42
S1_DCH064: length 161.7
  L03_DIG w0.132: v2(153.92,210.23) 155.65,208.5 164.76,208.5 204.86,168.4 204.86,92.95 197.16,85.25 197.16,80.05 195.85,78.74
S1_DCH065: length 225.1
  L22_DIG w0.076: v2(153.12,213.43) 153.52,213.83 154.27,213.83
  L22_DIG w0.132: 154.27,213.83 154.95,214.52 167.73,214.52 174.8,221.59 202.88,221.59 265.77,158.7 265.77,77.4 266.97,76.2
S1_DCH066: length 237.4
  L24_DIG w0.132: 264.43,58.42 263.29,59.56 263.29,125.85 240.67,148.47 240.67,178.49 198.16,221.01 174.5,221.01 167.32,213.83 154.32,213.83 v2(153.92,213.43)
S1_DCH067: length 204.3
  L05_DIG w0.076: v2(153.12,214.23) 153.52,214.63 154.27,214.63
  L05_DIG w0.132: 154.27,214.63 167.23,214.63 175.22,222.62 211.75,222.62 255.57,178.79 255.57,100.36 254.27,99.06
S1_DCH068: length 192.8
  L03_DIG w0.132: v2(153.92,214.23) 154.54,214.85 166.54,214.85 173.4,221.71 200.31,221.71 242.83,179.19 242.83,97.78 241.57,96.52
S1_DCH069: length 202.1
  L03_DIG w0.132: 246.65,96.52 247.94,97.81 247.94,136.19 247.04,137.08 247.04,183.9 205.25,225.7 169.27,225.7 164.25,220.68 161.06,220.68 158.6,218.22 154.71,218.22 v2(153.92,217.43)
S1_DCH070: length 246.7
  L24_DIG w0.132: 269.51,58.42 268.32,59.61 268.32,130.98 246.81,152.49 246.81,181.64 203.74,224.71 170.76,224.71 162.68,216.63 v2(153.92,216.63)
S1_DCH071: length 194.3
  L03_DIG w0.132: v2(153.92,215.83) 164.32,215.83 171.75,223.26 202.92,223.26 245.31,180.86 245.31,100.26 244.11,99.06
S1_DCH072: length 244.7
  L24_DIG w0.132: 266.97,55.88 265.82,57.03 265.82,128.4 244.05,150.17 244.05,180.39 201.86,222.59 173.84,222.59 166.28,215.03 v2(153.92,215.03)
S1_DCH073: length 247.6
  L22_DIG w0.076: v2(153.12,216.63) 153.52,217.03 154.27,217.03
  L22_DIG w0.132: 277.13,373.38 275.92,372.17 275.92,299.17 278.47,296.62 278.47,279.01 226.93,227.47 175.88,227.47 164.83,216.42 156.03,216.42 155.42,217.03 154.27,217.03
S1_DCH074: length 212.4
  L05_DIG w0.076: 154.27,216.23 153.52,216.23 v2(153.12,215.83)
  L05_DIG w0.132: 154.27,216.23 166.72,216.23 176.19,225.7 213.02,225.7 257.3,181.43 257.3,137.48 258.13,136.65 258.13,97.84 256.81,96.52
S1_DCH075: length 231.3
  L22_DIG w0.076: 154.27,215.43 153.52,215.43 v2(153.12,215.03)
  L22_DIG w0.132: 272.05,76.2 270.78,77.47 270.78,157.4 203.46,224.72 175.96,224.72 166.66,215.43 154.27,215.43
S1_DCH076: length 162.3
  L07_DIG w0.076: 154.27,217.03 152.72,217.03 v2(152.32,216.63)
  L07_DIG w0.132: 246.65,332.74 245.41,331.5 245.41,305.73 236.69,297.01 236.69,291.26 164.36,218.93 164.36,218.2 163.72,217.56 163.24,217.56 162.67,218.12 161.62,218.12 161.05,217.56 160.23,217.56 159.67,218.12 156.55,218.12 155.46,217.03 154.27,217.03
S1_DCH077: length 161.4
  L07_DIG w0.076: 154.27,216.23 152.72,216.23 v2(152.32,215.83)
  L07_DIG w0.132: 154.27,216.23 164.54,216.23 247.91,299.6 247.91,328.92 249.19,330.2
S1_DCH078: length 167.2
  L18_DIG w0.076: 154.27,217.03 151.92,217.03 v2(151.52,216.63)
  L18_DIG w0.132: 259.35,330.2 258.12,328.97 258.12,309.82 165.05,216.75 159.17,216.75 157.85,218.06 155.3,218.06 154.27,217.03
S1_DCH079: length 172.2
  L18_DIG w0.076: 154.27,216.23 151.92,216.23 v2(151.52,215.83)
  L18_DIG w0.132: 261.89,332.74 260.71,331.56 260.71,308.63 238.73,286.65 237.7,286.65 167.28,216.23 154.27,216.23
S1_DCH080: length 252.1
  L20_DIG w0.076: 154.27,213.84 151.13,213.84 v2(150.72,213.43)
  L20_DIG w0.132: 154.27,213.84 169.03,213.84 175.35,220.15 198.76,220.15 200.2,218.71 202.93,218.71 240.23,181.41 240.23,39.3 239.03,38.1
S1_DCH081: length 258.8
  L20_DIG w0.076: v2(150.72,214.23) 151.13,214.64 154.27,214.64
  L20_DIG w0.132: 154.27,214.64 168.33,214.64 175.22,221.53 204.02,221.53 242.67,182.87 242.67,36.66 241.57,35.56
S1_DCH082: length 260.9
  L20_DIG w0.076: v2(150.72,215.03) 151.13,215.44 154.27,215.44
  L20_DIG w0.132: 244.11,38.1 245.26,39.25 245.26,184.79 206.97,223.08 175.42,223.08 167.78,215.44 154.27,215.44
S1_DCH083: length 230.3
  L20_DIG w0.076: 154.27,216.24 151.13,216.24 v2(150.72,215.83)
  L20_DIG w0.132: 251.73,76.2 253.04,77.51 253.04,128.13 250.95,130.22 250.95,183.31 208.7,225.56 176.07,225.56 166.75,216.24 154.27,216.24
S1_DCH084: length 238.3
  L20_DIG w0.076: v2(150.72,216.63) 151.13,217.04 154.27,217.04
  L20_DIG w0.132: 154.27,217.04 155.17,217.04 156.44,218.31 157.49,218.31 159,216.8 164.85,216.8 167.1,219.04 167.98,219.04 177.87,228.94 209.19,228.94 256.16,181.97 256.16,129.9 258,128.06 258,77.39 256.81,76.2
S1_DCH085: length 171
  L07_DIG w0.076: v2(139.52,219.03) 139.12,219.43 138.55,219.43 138.29,219.68
  L07_DIG w0.132: 138.29,219.68 137.8,220.18 137.8,223.13 138.55,223.88 138.55,228.43 137.17,229.81 137.17,241.43 135.48,243.12 135.48,256.99 165.47,286.98 165.47,312.24 174.32,321.08 174.32,369.63 175.53,370.84
S1_DCH086: length 192.3
  L18_DIG w0.076: v2(140.32,218.23) 139.92,218.63 138.29,218.63
  L18_DIG w0.132: 175.53,391.16 174.25,389.88 174.25,314.86 135.66,276.28 135.66,233.67 137.71,231.62 137.71,219.21 138.29,218.63
S1_DCH087: length 126.7
  L03_DIG w0.132: 175.53,330.2 174.24,328.92 174.24,308.29 150.98,285.02 149.7,285.02 145.79,281.11 145.79,279.18 143.29,276.68 142.64,276.68 137.84,271.88 137.84,221.51 v2(138.72,220.63)
S1_DCH088: length 191.3
  L18_DIG w0.076: 140.72,222.61 140.72,220.23 v2(140.32,219.83)
  L18_DIG w0.132: 180.61,391.16 179.31,389.86 179.31,313.69 147.85,282.23 146.66,282.23 137.66,273.23 137.66,244.27 138.54,243.39 138.54,229.5 139.75,228.3 139.75,223.98 140.72,223.01 140.72,222.61
S1_DCH089: length 227.1
  L20_DIG w0.076: 141.53,222.58 141.53,219.44 v2(141.12,219.03)
  L20_DIG w0.132: 261.89,353.06 260.63,351.8 260.63,294.34 238.21,271.91 164.74,271.91 142.96,250.13 142.96,224.64 141.53,223.21 141.53,222.58
S1_DCH090: length 247.3
  L24_DIG w0.132: 249.19,391.16 247.97,389.94 247.97,305.18 230.85,288.05 230.85,286.54 208.8,264.49 154.61,264.49 140.32,250.2 140.32,237.48 138.43,235.59 138.43,229.64 140.32,227.75 v2(140.32,222.23)
S1_DCH091: length 170.5
  L07_DIG w0.076: 140.72,222.61 140.72,221.03 v2(140.32,220.63)
  L07_DIG w0.132: 183.15,373.38 181.97,372.2 181.97,318.37 173.79,310.19 173.79,286.24 142.39,254.84 142.39,224.27 140.72,222.61
S1_DCH092: length 191.2
  L18_DIG w0.076: v2(141.92,219.83) 142.32,220.23 142.32,222.58
  L18_DIG w0.132: 142.32,222.58 142.76,223.02 142.76,237.61 140.64,239.73 140.64,268.18 142.76,270.3 142.76,271.31 163.17,291.72 163.17,292.37 184.44,313.65 184.44,389.91 185.69,391.16
S1_DCH093: length 240.6
  L24_DIG w0.132: v2(138.72,219.83) 137.37,221.18 137.37,254.34 152.18,269.15 194.02,269.15 204.54,279.67 204.54,281.13 242.94,319.52 242.94,389.99 244.11,391.16
S1_DCH094: length 172.8
  L07_DIG w0.076: 138.37,222.61 138.37,220.46 138.6,220.23 139.12,220.23 v2(139.52,219.83)
  L07_DIG w0.132: 178.07,373.38 176.75,372.06 176.75,320.37 167.88,311.49 167.88,285.84 137.4,255.36 137.4,243.5 137.89,243.01 137.89,229.87 139.79,227.97 139.79,224.02 138.37,222.61
S1_DCH095: length 247.8
  L24_DIG w0.132: 246.65,393.7 245.52,392.57 245.52,306.27 205.94,266.69 154.23,266.69 139.16,251.62 139.16,244.12 138.05,243 138.05,222.1 v2(138.72,221.43)
S1_DCH096: length 193.7
  L18_DIG w0.076: 138.29,219.73 138.6,219.43 139.92,219.43 v2(140.32,219.03)
  L18_DIG w0.132: 138.29,219.73 138.2,219.82 138.2,232.2 137.17,233.24 137.17,274.7 176.81,314.35 176.81,392.44 178.07,393.7
S1_DCH097: length 127.1
  L03_DIG w0.132: v2(139.52,222.23) 140.4,223.11 140.4,227.74 142.28,229.62 142.28,237.23 140.33,239.19 140.33,268.33 163.21,291.21 164.01,291.21 165.61,292.81 165.61,294.32 179.35,308.05 179.35,328.94 180.61,330.2
S1_DCH098: length 224.5
  L22_DIG w0.076: 140.72,222.61 140.72,221.83 v2(140.32,221.43)
  L22_DIG w0.132: 249.19,370.84 248.11,369.76 248.11,305.67 230.32,287.88 230.32,286.63 207.1,263.41 155.84,263.41 142.44,250.01 142.44,224.32 140.72,222.61
S1_DCH099: length 251.2
  L24_DIG w0.076: v2(141.12,221.43) 141.52,221.83 141.52,222.61
  L24_DIG w0.132: 141.52,222.61 141.52,223.73 142.42,224.63 142.42,249.33 156.07,262.98 211.05,262.98 234.71,286.64 236.26,286.64 250.55,300.93 250.55,392.52 251.73,393.7
S1_DCH100: length 176.8
  L07_DIG w0.076: v2(139.52,216.63) 139.12,217.03 138.29,217.03
  L07_DIG w0.132: 167.91,373.38 166.67,372.14 166.67,321.44 159.24,314.01 159.24,287.35 130.67,258.78 130.67,240.06 135.08,235.64 135.08,229.73 136.59,228.22 136.59,225.31 135.98,224.7 135.98,219.34 138.29,217.03
S1_DCH101: length 187.8
  L20_DIG w0.076: 138.29,217.03 140.72,217.03 v2(141.12,217.43)
  L20_DIG w0.132: 138.29,217.03 137.92,217.03 136.84,218.11 136.84,222.39 138.53,224.08 138.53,242.5 139.4,243.38 139.4,254.63 202.34,317.57 202.34,372.25 203.47,373.38
S1_DCH102: length 231.5
  L20_DIG w0.076: v2(141.12,218.23) 140.72,217.83 138.29,217.83
  L20_DIG w0.132: 138.29,217.83 137.93,218.19 137.93,222.45 138.44,222.96 139.59,222.96 140.4,223.77 140.4,227.67 142.52,229.79 142.52,235.51 140.4,237.63 140.4,250.1 164.38,274.09 237.78,274.09 258.13,294.44 258.13,349.3 259.35,350.52
S1_DCH103: length 169.6
  L07_DIG w0.076: v2(139.52,220.63) 139.92,221.03 139.92,222.61
  L07_DIG w0.132: 180.61,370.84 179.39,369.62 179.39,319.85 171.08,311.55 171.08,286.64 139.48,255.04 139.48,243.19 140.48,242.2 140.48,237.44 138.55,235.51 138.55,229.85 140.48,227.93 140.48,223.16 139.92,222.61
S1_DCH104: length 127.9
  L03_DIG w0.132: 178.07,332.74 176.82,331.49 176.82,308.23 161.91,293.33 161.24,293.33 160.16,292.25 160.16,291.57 149.75,281.16 149.75,280.58 146.25,277.08 145.67,277.08 139.46,270.87 139.46,242.78 138.34,241.67 138.34,222.61 v2(138.72,222.23)
S1_DCH105: length 127.9
  L03_DIG w0.132: v2(141.12,222.23) 142.89,224 142.89,264.25 181.88,303.24 181.88,331.47 183.15,332.74
S1_DCH106: length 169.8
  L07_DIG w0.076: v2(141.12,220.63) 141.52,221.03 141.52,222.61
  L07_DIG w0.132: 141.52,222.61 142.95,224.03 142.95,253.14 170.86,281.05 172.76,281.05 173.76,282.06 173.76,285.21 184.43,295.88 184.43,369.58 185.69,370.84
S1_DCH107: length 129.9
  L03_DIG w0.132: v2(138.72,216.63) 136.96,218.39 136.96,233.52 134.92,235.56 134.92,275.39 169.23,309.69 169.23,328.98 170.45,330.2
S1_DCH108: length 148.2
  L05_DIG w0.076: 138.29,217.86 v2(138.72,217.43)
  L05_DIG w0.132: 170.45,350.52 169.23,349.3 169.23,303.37 151.51,285.65 150.21,285.65 137.24,272.67 137.24,233.41 137.88,232.77 137.88,218.27 138.29,217.86
S1_DCH109: length 146.8
  L05_DIG w0.076: 139.92,222.61 139.92,221.83 v2(139.52,221.43)
  L05_DIG w0.132: 139.92,222.61 139.92,228.06 138.34,229.64 138.34,237.51 139.92,239.09 139.92,271.04 159.69,290.81 159.69,291.42 171.74,303.47 171.74,351.81 172.99,353.06
